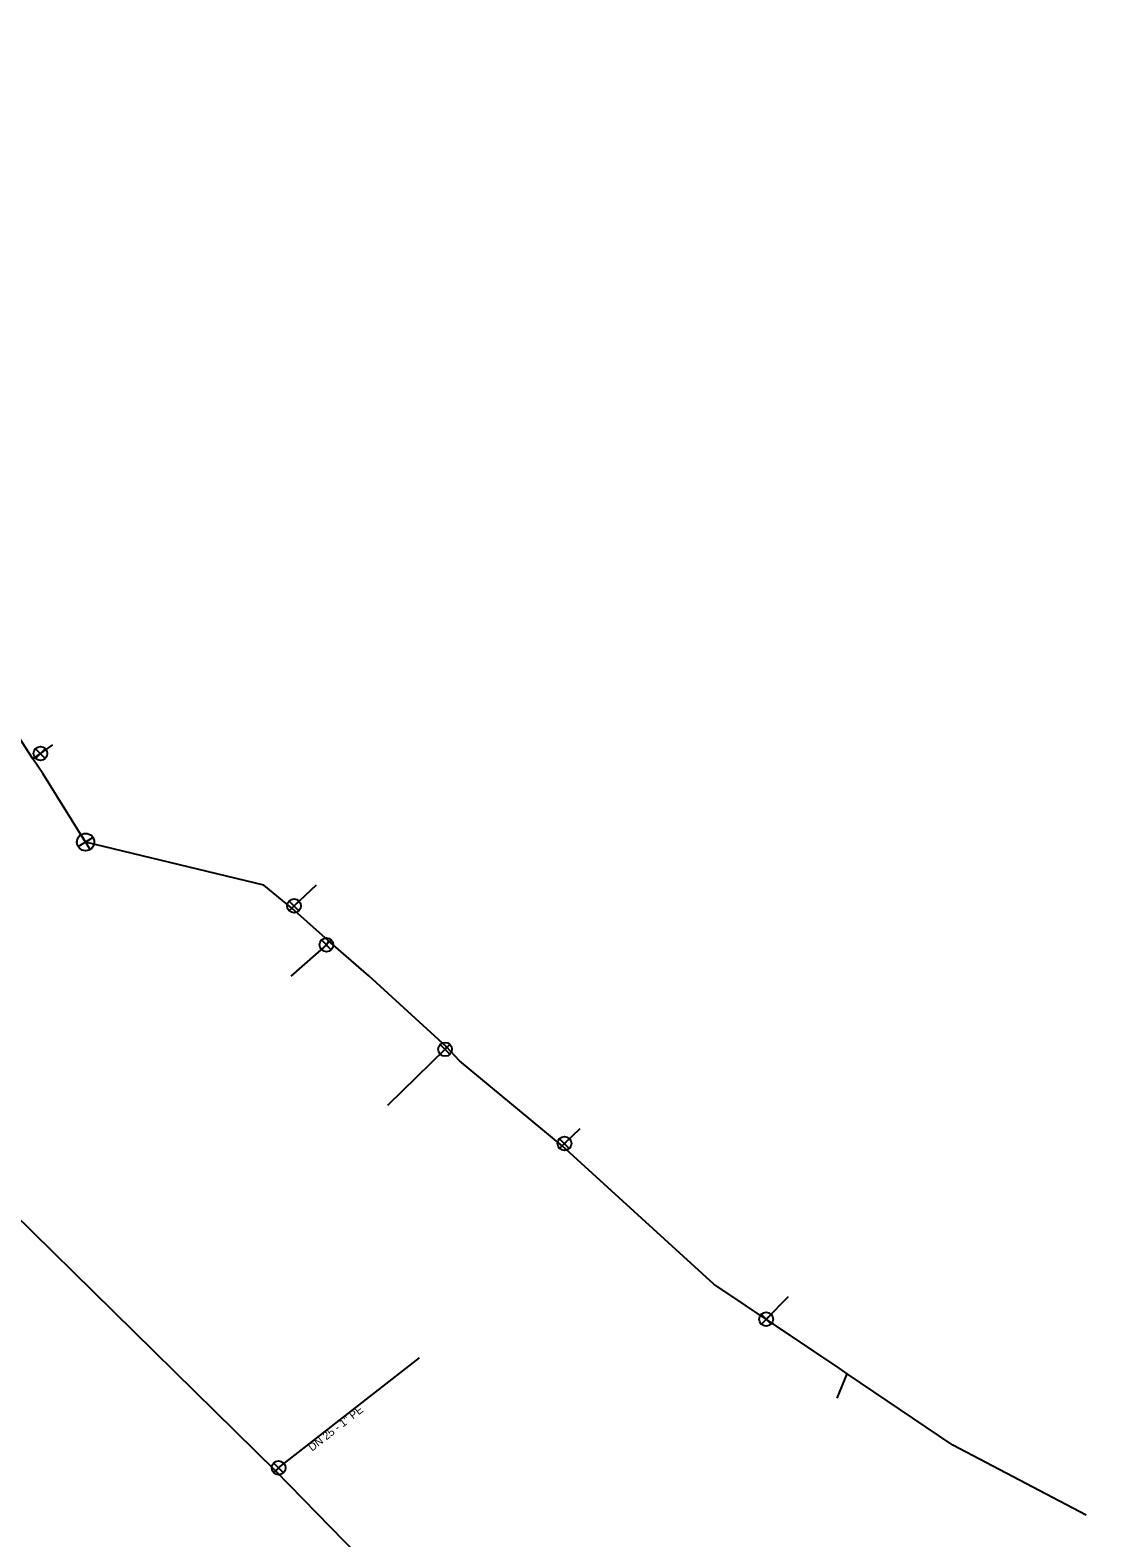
# Model space of a CAD drawing. Extents: x -484784 to -484458, y -1128042 to -1127614.
# Drawn here: x -484646.3 to -484583.5, y -1127805.6 to -1127718.4 of the extents above; entities that cross this region are included whole.
import ezdxf

# ---------------------------------------------------------------- set-up
doc = ezdxf.new("R2010")
doc.units = 0
for name, color, linetype in [('_pripojka_prevzato_z_dokumentace_', 7, 'Continuous'), ('_pripojka_priblizne_', 7, 'Continuous'), ('_voda_smvak_prevzato_z_dokumentace_', 7, 'Continuous'), ('Default', 7, 'Continuous'), ('MoLevel 27', 7, 'Continuous'), ('MoLevel 53', 7, 'Continuous'), ('MoLevel 55', 7, 'Continuous')]:
    doc.layers.add(name, color=color, linetype=linetype)

# ---------------------------------------------------------------- blocks, each defined once
blk = doc.blocks.new('_uzaver_')
at = {"layer": 'Default'}
for p, q in [((-0.000035, -0.000035), (0.000035, 0.000035)), ((0.000035, -0.000035), (-0.000035, 0.000035))]:
    blk.add_line(p, q, dxfattribs=at)
for radius in [0.00005, 0.0000025]:
    blk.add_circle((0, 0), radius, dxfattribs=at)
blk = doc.blocks.new('_uzaver_pripojka_')
at = {"layer": 'Default'}
for p, q in [((-0.000035, -0.000035), (0.000035, 0.000035)), ((0.000035, -0.000035), (-0.000035, 0.000035))]:
    blk.add_line(p, q, dxfattribs=at)
for radius in [0.00005, 0.0000025]:
    blk.add_circle((0, 0), radius, dxfattribs=at)

msp = doc.modelspace()

# ---------------------------------------------------------------- linework, layer by layer
at = {"layer": '_pripojka_prevzato_z_dokumentace_'}
for points in [[(-484646.121, -1127760.523), (-484645.69, -1127760.22), (-484644.967, -1127759.711)], [(-484631.161, -1127769.165), (-484631.03, -1127769.03), (-484629.732, -1127767.818)], [(-484629.046, -1127771.058), (-484629.16, -1127771.28), (-484631.218, -1127773.099)], [(-484622.225, -1127777.17), (-484622.3, -1127777.32), (-484625.631, -1127780.569)], [(-484615.535, -1127782.894), (-484615.4, -1127782.77), (-484614.496, -1127781.89)], [(-484599.525, -1127795.757), (-484603.738, -1127792.924), (-484602.446, -1127791.615)], [(-484632.109, -1127801.7), (-484631.92, -1127801.52), (-484623.781, -1127795.156)]]:
    msp.add_lwpolyline(points, dxfattribs=at)
at = {"layer": '_pripojka_priblizne_'}
msp.add_line((-484599.635, -1127797.492), (-484599.059, -1127796.076), dxfattribs=at)
at = {"layer": '_voda_smvak_prevzato_z_dokumentace_'}
for points in [[(-484643.08, -1127765.34), (-484645.558, -1127761.377), (-484646.121, -1127760.523), (-484650.612, -1127753.602), (-484650.955, -1127753.108), (-484652.744, -1127750.288), (-484654.582, -1127747.805), (-484659.496, -1127741.98), (-484663.295, -1127738.246), (-484667.445, -1127734.471), (-484668.218, -1127733.675), (-484673.26, -1127728.099), (-484673.76, -1127727.546), (-484675.038, -1127726.215), (-484681.24, -1127716.168), (-484682.755, -1127712.65), (-484683.576, -1127711.276), (-484684.331, -1127709.732), (-484687.857, -1127701.916), (-484687.921, -1127701.756), (-484691.708, -1127695.751), (-484698.386, -1127690.884), (-484712.097, -1127682.86)], [(-484585.245, -1127804.256), (-484592.952, -1127800.204), (-484599.059, -1127796.076), (-484599.525, -1127795.757), (-484606.767, -1127790.907), (-484615.535, -1127782.894), (-484621.464, -1127777.986), (-484622.225, -1127777.17), (-484626.698, -1127773.076), (-484629.046, -1127771.058), (-484631.161, -1127769.165), (-484632.783, -1127767.838), (-484643.08, -1127765.34)], [(-484648.492, -1127785.585), (-484632.109, -1127801.7), (-484625, -1127808.969), (-484624.296, -1127809.744), (-484623.356, -1127810.97), (-484621.849, -1127813.136), (-484618.11, -1127819.53), (-484617.65, -1127820.12), (-484615.463, -1127823.691), (-484611.477, -1127830.067), (-484610.397, -1127831.791), (-484608.509, -1127835.039), (-484607.695, -1127835.947), (-484607.546, -1127836.169), (-484599.55, -1127849.979), (-484596.391, -1127855.236), (-484593.245, -1127859.963), (-484588.208, -1127868.192), (-484587.397, -1127869.371), (-484583.472, -1127874.589)]]:
    msp.add_lwpolyline(points, dxfattribs=at)

# ---------------------------------------------------------------- block references
at = {"layer": 'MoLevel 27', "xscale": 10000.000000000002, "yscale": 10000, "rotation": -13.64279895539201}
msp.add_blockref('_uzaver_', (-484643.08, -1127765.34), dxfattribs=at)
at = {"layer": 'MoLevel 53', "xscale": 7999.999999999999, "yscale": 7999.999999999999}
for p in [(-484645.69, -1127760.22), (-484631.03, -1127769.03), (-484629.16, -1127771.28), (-484622.3, -1127777.32), (-484615.4, -1127782.77), (-484603.738, -1127792.924), (-484631.92, -1127801.52)]:
    msp.add_blockref('_uzaver_pripojka_', p, dxfattribs=at)

# ---------------------------------------------------------------- texts
at = {"layer": 'MoLevel 55'}
msp.add_text("DN 25 - 1'' PE", height=0.455, rotation=38.02236, dxfattribs=at).set_placement((-484629.986, -1127800.585))

doc.saveas('drawing.dxf')
